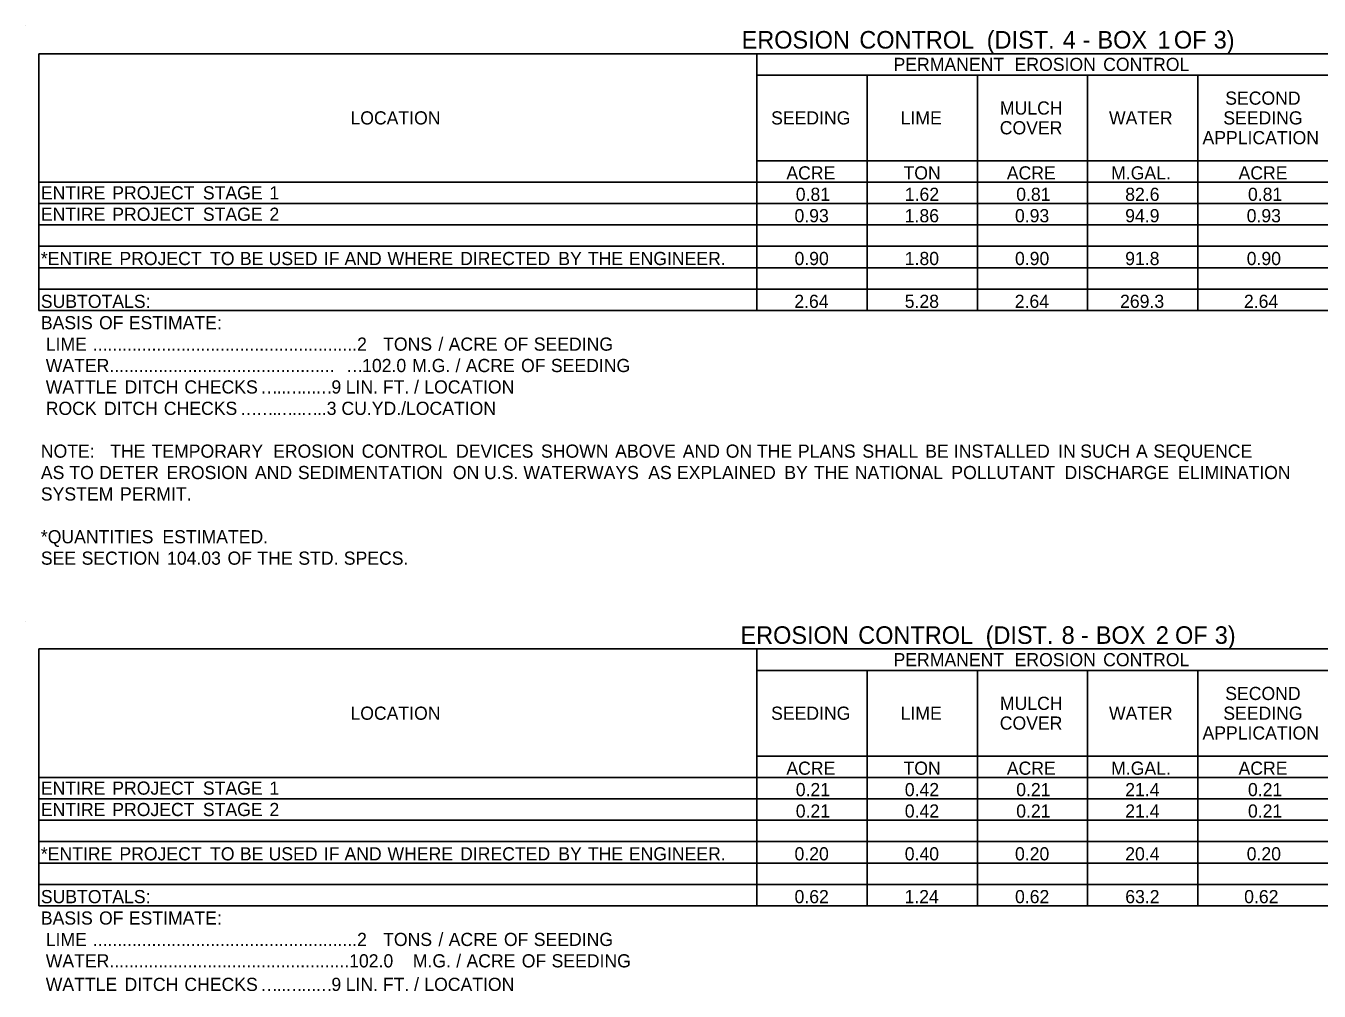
# Model space of a CAD drawing. Extents: x 540541 to 1930787, y -1948574 to 596640.
# Drawn here: x 546410 to 546999, y -1948060 to -1947621 of the extents above; entities that cross this region are included whole.
import ezdxf

# ---------------------------------------------------------------- set-up
doc = ezdxf.new("R2010")
doc.units = 0
doc.layers.add('Default', color=7, linetype='Continuous')
doc.layers.add('R_Border', color=7, linetype='Continuous')

msp = doc.modelspace()

# ---------------------------------------------------------------- linework, layer by layer
at = {"layer": 'Default'}
for p, q in [((546415.64, -1947633.26), (547286.32, -1947633.26)), ((546415.64, -1947750.26), (546415.64, -1947633.26)), ((546415.64, -1947750.26), (546415.64, -1947633.26)), ((546742.75, -1947750.26), (546742.75, -1947633.26)), ((546742.75, -1947643.01), (547286.32, -1947643.01)), ((546792.97, -1947750.26), (546792.97, -1947643.01)), ((546843.18, -1947750.26), (546843.18, -1947643.01)), ((546893.39, -1947750.26), (546893.39, -1947643.01)), ((546943.6, -1947750.26), (546943.6, -1947643.01)), ((546742.75, -1947682.01), (547226.35, -1947682.01)), ((546792.97, -1947750.26), (546792.97, -1947682.01)), ((546843.18, -1947740.51), (546843.18, -1947682.01)), ((546893.39, -1947740.51), (546893.39, -1947682.01)), ((546943.6, -1947740.51), (546943.6, -1947682.01)), ((546415.64, -1947691.76), (547286.32, -1947691.76)), ((546415.64, -1947701.51), (547286.32, -1947701.51)), ((546415.64, -1947711.26), (547286.32, -1947711.26)), ((546415.64, -1947721.01), (547286.32, -1947721.01)), ((546415.64, -1947730.76), (547286.32, -1947730.76)), ((546415.64, -1947740.51), (547126.42, -1947740.51)), ((546742.75, -1947750.26), (546742.75, -1947740.51)), ((546792.97, -1947740.51), (547004.05, -1947740.51)), ((546415.64, -1947750.26), (547286.32, -1947750.26)), ((546415.64, -1947904.44), (547286.32, -1947904.44)), ((546415.64, -1948021.44), (546415.64, -1947904.44)), ((546415.64, -1948021.44), (546415.64, -1947904.44)), ((546742.75, -1948021.44), (546742.75, -1947904.44)), ((546742.75, -1947914.19), (547286.32, -1947914.19)), ((546792.97, -1948021.44), (546792.97, -1947914.19)), ((546843.18, -1948021.44), (546843.18, -1947914.19)), ((546893.39, -1948021.44), (546893.39, -1947914.19)), ((546943.6, -1948021.44), (546943.6, -1947914.19)), ((546742.75, -1947953.19), (547226.35, -1947953.19)), ((546792.97, -1948021.44), (546792.97, -1947953.19)), ((546843.18, -1948011.69), (546843.18, -1947953.19)), ((546893.39, -1948011.69), (546893.39, -1947953.19)), ((546943.6, -1948011.69), (546943.6, -1947953.19)), ((546415.64, -1947962.94), (547286.32, -1947962.94)), ((546415.64, -1947972.69), (547286.32, -1947972.69)), ((546415.64, -1947982.44), (547286.32, -1947982.44)), ((546415.64, -1947992.19), (547286.32, -1947992.19)), ((546415.64, -1948001.94), (547286.32, -1948001.94)), ((546415.64, -1948011.69), (547126.42, -1948011.69)), ((546742.75, -1948021.44), (546742.75, -1948011.69)), ((546792.97, -1948011.69), (547004.05, -1948011.69)), ((546415.64, -1948021.44), (547286.32, -1948021.44))]:
    msp.add_line(p, q, dxfattribs=at)
at = {"layer": 'R_Border'}
for p, q in [((546409.79, -1947620.59), (546409.79, -1947620.59)), ((546409.79, -1947891.76), (546409.79, -1947891.76))]:
    msp.add_line(p, q, dxfattribs=at)

# ---------------------------------------------------------------- texts
at = {"layer": 'Default'}
for s, height, p in [('EROSION', 8, (546735.8, -1947630.93)), (' CONTROL', 8, (546786.46, -1947630.93)), (' (DIST.', 8, (546844.49, -1947630.93)), (' 4', 8, (546879.11, -1947630.93)), (' BOX', 8, (546894.92, -1947630.93)), (' 1', 8, (546922.24, -1947630.93)), (' OF', 8, (546929.74, -1947630.93)), (' 3)', 8, (546947.85, -1947630.93)), (' -', 8, (546888.18, -1947630.93)), ('PERMANENT', 6, (546805.01, -1947641.14)), (' EROSION', 6, (546857.94, -1947641.14)), (' CONTROL', 6, (546898.27, -1947641.14)), ('MULCH', 6, (546853.47, -1947661.01)), ('SECOND', 6, (546956.1, -1947656.51)), ('LOCATION', 6, (546557.64, -1947665.51)), ('SEEDING', 6, (546749.24, -1947665.51)), ('LIME', 6, (546808.27, -1947665.51)), ('WATER', 6, (546903.15, -1947665.51)), ('SEEDING', 6, (546955.21, -1947665.51)), ('COVER', 6, (546853.4, -1947670.01)), ('APPLICATION', 6, (546945.75, -1947674.51)), ('ACRE', 6, (546756.19, -1947690.56)), ('TON', 6, (546809.56, -1947690.56)), ('ACRE', 6, (546856.61, -1947690.56)), ('M.GAL.', 6, (546904.12, -1947690.56)), ('ACRE', 6, (546962.16, -1947690.56)), ('ENTIRE', 6, (546416.62, -1947699.64)), (' PROJECT', 6, (546446.91, -1947699.64)), (' STAGE', 6, (546488.2, -1947699.64)), (' 1', 6, (546518.51, -1947699.64)), ('0.81', 6, (546760.48, -1947700.31)), ('1.62', 6, (546810.14, -1947700.31)), ('0.81', 6, (546860.9, -1947700.31)), ('82.6', 6, (546910.53, -1947700.31)), ('0.81', 6, (546966.45, -1947700.31)), ('ENTIRE', 6, (546416.62, -1947709.39)), (' PROJECT', 6, (546446.91, -1947709.39)), (' STAGE', 6, (546488.2, -1947709.39)), (' 2', 6, (546518.51, -1947709.39)), ('0.93', 6, (546759.9, -1947710.06)), ('1.86', 6, (546810.11, -1947710.06)), ('0.93', 6, (546860.32, -1947710.06)), ('94.9', 6, (546910.53, -1947710.06)), ('0.93', 6, (546965.86, -1947710.06)), ('*ENTIRE', 6, (546416.62, -1947729.56)), (' PROJECT', 6, (546450.17, -1947729.56)), (' TO', 6, (546491.47, -1947729.56)), (' BE', 6, (546505.06, -1947729.56)), (' USED', 6, (546518.13, -1947729.56)), (' IF', 6, (546543.3, -1947729.56)), (' AND', 6, (546552.7, -1947729.56)), (' WHERE', 6, (546572.28, -1947729.56)), (' DIRECTED', 6, (546605.36, -1947729.56)), (' BY', 6, (546650.1, -1947729.56)), (' THE', 6, (546663.55, -1947729.56)), (' ENGINEER.', 6, (546682.2, -1947729.56)), ('0.90', 6, (546759.91, -1947729.56)), ('1.80', 6, (546810.12, -1947729.56)), ('0.90', 6, (546860.33, -1947729.56)), ('91.8', 6, (546910.53, -1947729.56)), ('0.90', 6, (546965.88, -1947729.56)), ('SUBTOTALS:', 6, (546416.62, -1947749.06)), ('2.64', 6, (546759.8, -1947749.06)), ('5.28', 6, (546810.11, -1947749.06)), ('2.64', 6, (546860.23, -1947749.06)), ('269.3', 6, (546908.19, -1947749.06)), ('2.64', 6, (546964.61, -1947749.06)), ('BASIS', 6, (546416.62, -1947758.81)), (' OF', 6, (546440.88, -1947758.81)), (' ESTIMATE:', 6, (546454.46, -1947758.81)), (' LIME', 6, (546416.62, -1947768.56)), (' ......................................................2', 6, (546438.06, -1947768.56)), (' TONS', 6, (546570.3, -1947768.56)), (' /', 6, (546595.48, -1947768.56)), (' ACRE', 6, (546600.14, -1947768.56)), (' OF', 6, (546625.32, -1947768.56)), (' SEEDING', 6, (546638.9, -1947768.56)), (' WATER..............................................', 6, (546416.62, -1947778.31)), ('102.0', 6, (546562.96, -1947778.31)), (' M.G.', 6, (546583.53, -1947778.31)), (' /', 6, (546603.28, -1947778.31)), (' ACRE', 6, (546607.94, -1947778.31)), (' OF', 6, (546633.12, -1947778.31)), (' SEEDING', 6, (546646.71, -1947778.31)), ('…', 6, (546555.56, -1947778.31)), (' WATTLE', 6, (546416.62, -1947788.06)), (' DITCH', 6, (546452.5, -1947788.06)), (' CHECKS', 6, (546479.76, -1947788.06)), ('9', 6, (546548.97, -1947788.06)), (' LIN.', 6, (546553.26, -1947788.06)), (' FT.', 6, (546570.22, -1947788.06)), (' /', 6, (546584.39, -1947788.06)), (' LOCATION', 6, (546589.05, -1947788.06)), ('…', 6, (546516.59, -1947788.06)), ('..', 6, (546523.99, -1947788.06)), ('…', 6, (546527.92, -1947788.06)), ('...', 6, (546535.32, -1947788.06)), ('…', 6, (546541.57, -1947788.06)), (' ROCK', 6, (546416.62, -1947797.81)), (' DITCH', 6, (546443.15, -1947797.81)), (' CHECKS', 6, (546470.41, -1947797.81)), ('..3', 6, (546542.36, -1947797.81)), (' CU.YD./LOCATION', 6, (546551.3, -1947797.81)), ('…', 6, (546507.25, -1947797.81)), ('…', 6, (546514.65, -1947797.81)), ('.', 6, (546522.05, -1947797.81)), ('…', 6, (546523.64, -1947797.81)), ('..', 6, (546531.04, -1947797.81)), ('…', 6, (546534.97, -1947797.81)), ('NOTE:', 6, (546416.62, -1947817.31)), ('   THE', 6, (546441.5, -1947817.31)), (' TEMPORARY', 6, (546464.81, -1947817.31)), (' EROSION', 6, (546520.18, -1947817.31)), (' CONTROL', 6, (546560.49, -1947817.31)), (' DEVICES', 6, (546603.51, -1947817.31)), (' SHOWN', 6, (546642.21, -1947817.31)), (' ABOVE', 6, (546675.98, -1947817.31)), (' AND', 6, (546706.76, -1947817.31)), (' ON', 6, (546726.34, -1947817.31)), (' THE', 6, (546740.56, -1947817.31)), (' PLANS', 6, (546759.21, -1947817.31)), (' SHALL', 6, (546788.59, -1947817.31)), (' BE', 6, (546817.18, -1947817.31)), (' INSTALLED', 6, (546830.25, -1947817.31)), (' IN', 6, (546877.78, -1947817.31)), (' SUCH', 6, (546887.81, -1947817.31)), (' A', 6, (546913.22, -1947817.31)), (' SEQUENCE', 6, (546921.15, -1947817.31)), ('AS', 6, (546416.62, -1947827.06)), (' TO', 6, (546427.36, -1947827.06)), (' DETER', 6, (546440.96, -1947827.06)), (' EROSION', 6, (546471.59, -1947827.06)), (' AND', 6, (546511.9, -1947827.06)), (' SEDIMENTATION', 6, (546531.48, -1947827.06)), (' ON', 6, (546602.06, -1947827.06)), (' U.S.', 6, (546616.28, -1947827.06)), (' WATERWAYS', 6, (546634.18, -1947827.06)), (' AS', 6, (546691.03, -1947827.06)), (' EXPLAINED', 6, (546704.11, -1947827.06)), (' BY', 6, (546753.05, -1947827.06)), (' THE', 6, (546766.5, -1947827.06)), (' NATIONAL', 6, (546785.15, -1947827.06)), (' POLLUTANT', 6, (546829.11, -1947827.06)), (' DISCHARGE', 6, (546880.65, -1947827.06)), (' ELIMINATION', 6, (546932.37, -1947827.06)), ('SYSTEM', 6, (546416.62, -1947836.81)), (' PERMIT.', 6, (546450.46, -1947836.81)), ('*QUANTITIES', 6, (546416.62, -1947856.31)), (' ESTIMATED.', 6, (546469.75, -1947856.31)), ('SEE', 6, (546416.62, -1947866.06)), (' SECTION', 6, (546432.95, -1947866.06)), (' 104.03', 6, (546471.86, -1947866.06)), (' OF', 6, (546499.43, -1947866.06)), (' THE', 6, (546513.02, -1947866.06)), (' STD.', 6, (546531.67, -1947866.06)), (' SPECS.', 6, (546552.36, -1947866.06)), ('EROSION', 8, (546735.29, -1947902.1)), (' CONTROL', 8, (546785.95, -1947902.1)), (' (DIST.', 8, (546843.99, -1947902.1)), (' 8', 8, (546878.61, -1947902.1)), (' BOX', 8, (546894.17, -1947902.1)), (' 2', 8, (546921.49, -1947902.1)), (' OF', 8, (546930.25, -1947902.1)), (' 3)', 8, (546948.36, -1947902.1)), (' -', 8, (546887.43, -1947902.1)), ('PERMANENT', 6, (546805.01, -1947912.31)), (' EROSION', 6, (546857.94, -1947912.31)), (' CONTROL', 6, (546898.27, -1947912.31)), ('MULCH', 6, (546853.47, -1947932.19)), ('SECOND', 6, (546956.1, -1947927.69)), ('LOCATION', 6, (546557.64, -1947936.69)), ('SEEDING', 6, (546749.24, -1947936.69)), ('LIME', 6, (546808.27, -1947936.69)), ('WATER', 6, (546903.15, -1947936.69)), ('SEEDING', 6, (546955.21, -1947936.69)), ('COVER', 6, (546853.4, -1947941.19)), ('APPLICATION', 6, (546945.75, -1947945.69)), ('ACRE', 6, (546756.19, -1947961.74)), ('TON', 6, (546809.56, -1947961.74)), ('ACRE', 6, (546856.61, -1947961.74)), ('M.GAL.', 6, (546904.12, -1947961.74)), ('ACRE', 6, (546962.16, -1947961.74)), ('ENTIRE', 6, (546416.62, -1947970.81)), (' PROJECT', 6, (546446.91, -1947970.81)), (' STAGE', 6, (546488.2, -1947970.81)), (' 1', 6, (546518.51, -1947970.81)), ('0.21', 6, (546760.48, -1947971.49)), ('0.42', 6, (546810.14, -1947971.49)), ('0.21', 6, (546860.9, -1947971.49)), ('21.4', 6, (546910.55, -1947971.49)), ('0.21', 6, (546966.45, -1947971.49)), ('ENTIRE', 6, (546416.62, -1947980.56)), (' PROJECT', 6, (546446.91, -1947980.56)), (' STAGE', 6, (546488.2, -1947980.56)), (' 2', 6, (546518.51, -1947980.56)), ('0.21', 6, (546760.48, -1947981.24)), ('0.42', 6, (546810.14, -1947981.24)), ('0.21', 6, (546860.9, -1947981.24)), ('21.4', 6, (546910.55, -1947981.24)), ('0.21', 6, (546966.45, -1947981.24)), ('*ENTIRE', 6, (546416.62, -1948000.74)), (' PROJECT', 6, (546450.17, -1948000.74)), (' TO', 6, (546491.47, -1948000.74)), (' BE', 6, (546505.06, -1948000.74)), (' USED', 6, (546518.13, -1948000.74)), (' IF', 6, (546543.3, -1948000.74)), (' AND', 6, (546552.7, -1948000.74)), (' WHERE', 6, (546572.28, -1948000.74)), (' DIRECTED', 6, (546605.36, -1948000.74)), (' BY', 6, (546650.1, -1948000.74)), (' THE', 6, (546663.55, -1948000.74)), (' ENGINEER.', 6, (546682.2, -1948000.74)), ('0.20', 6, (546759.91, -1948000.74)), ('0.40', 6, (546810.12, -1948000.74)), ('0.20', 6, (546860.33, -1948000.74)), ('20.4', 6, (546910.55, -1948000.74)), ('0.20', 6, (546965.88, -1948000.74)), ('SUBTOTALS:', 6, (546416.62, -1948020.24)), ('0.62', 6, (546759.92, -1948020.24)), ('1.24', 6, (546810.01, -1948020.24)), ('0.62', 6, (546860.34, -1948020.24)), ('63.2', 6, (546910.55, -1948020.24)), ('0.62', 6, (546964.72, -1948020.24)), ('BASIS', 6, (546416.62, -1948029.99)), (' OF', 6, (546440.88, -1948029.99)), (' ESTIMATE:', 6, (546454.46, -1948029.99)), (' LIME', 6, (546416.62, -1948039.74)), (' ......................................................2', 6, (546438.06, -1948039.74)), (' TONS', 6, (546570.3, -1948039.74)), (' /', 6, (546595.48, -1948039.74)), (' ACRE', 6, (546600.14, -1948039.74)), (' OF', 6, (546625.32, -1948039.74)), (' SEEDING', 6, (546638.9, -1948039.74)), (' WATER.................................................102.0', 6, (546416.62, -1948049.49)), (' M.G.', 6, (546583.84, -1948049.49)), (' /', 6, (546603.6, -1948049.49)), (' ACRE', 6, (546608.26, -1948049.49)), (' OF', 6, (546633.43, -1948049.49)), (' SEEDING', 6, (546647.02, -1948049.49)), (' WATTLE', 6, (546416.62, -1948060.21)), (' DITCH', 6, (546452.5, -1948060.21)), (' CHECKS', 6, (546479.76, -1948060.21)), ('9', 6, (546548.97, -1948060.21)), (' LIN.', 6, (546553.26, -1948060.21)), (' FT.', 6, (546570.22, -1948060.21)), (' /', 6, (546584.39, -1948060.21)), (' LOCATION', 6, (546589.05, -1948060.21)), ('…', 6, (546516.59, -1948060.21)), ('..', 6, (546523.99, -1948060.21)), ('…', 6, (546527.92, -1948060.21)), ('...', 6, (546535.32, -1948060.21)), ('…', 6, (546541.57, -1948060.21))]:
    msp.add_text(s, height=height, dxfattribs=at).set_placement(p)

doc.saveas('drawing.dxf')
